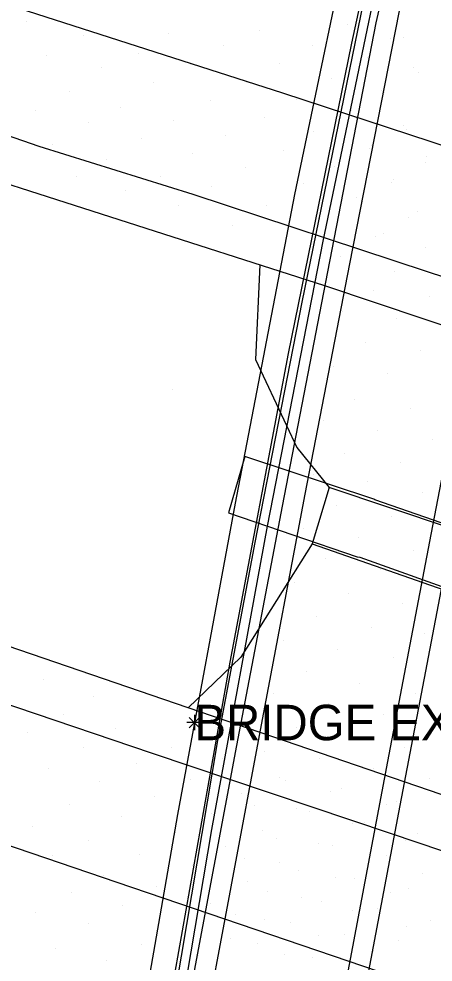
# Model space of a CAD drawing. Extents: x 1733582 to 1734070, y 467256 to 468256.
# Drawn here: x 1733820.12 to 1733841.15, y 467736.94 to 467784.83 of the extents above; entities that cross this region are included whole.
import ezdxf

# ---------------------------------------------------------------- set-up
doc = ezdxf.new("R2010")
doc.units = 0
for name, color, linetype in [('Default', 7, 'Continuous'), ('S_Bridge_Column_Square', 7, 'Continuous'), ('S_Bridge_Curb', 7, 'Continuous'), ('S_Bridge_Deck', 7, 'Continuous'), ('S_Bridge_Rail', 7, 'Continuous'), ('S_Ground_LevelString', 7, 'Continuous'), ('S_Ground_SpotElevation', 7, 'Continuous'), ('S_Guardrail_Beam', 7, 'Continuous'), ('S_Misc_MiscFeature', 7, 'Continuous'), ('S_Misc_MiscItems', 7, 'Continuous'), ('S_Roadway_Edge_Pavement', 7, 'Continuous'), ('S_Roadway_Painted_Lines', 7, 'Continuous'), ('S_Text', 7, 'Continuous')]:
    doc.layers.add(name, color=color, linetype=linetype)

# ---------------------------------------------------------------- blocks, each defined once
blk = doc.blocks.new('POINT_DISPLAY')
at = {"layer": 'Default'}
blk.add_line((0, 0), (0, 0), dxfattribs=at)

msp = doc.modelspace()

# ---------------------------------------------------------------- linework, layer by layer
at = {"layer": 'S_Bridge_Column_Square'}
msp.add_lwpolyline([(1733835.014, 467758.174), (1733846.976, 467754), (1733861.457, 467749.164), (1733862.347, 467752.05), (1733848.201, 467756.91), (1733835.866, 467761.044), (1733835.014, 467758.174)], dxfattribs=at)
at = {"layer": 'S_Bridge_Curb'}
msp.add_lwpolyline([(1733818.159, 467663.732), (1733819.385, 467674.582), (1733820.64, 467684.116), (1733822.243, 467697.564), (1733823.972, 467709.579), (1733825.87, 467722.342), (1733827.859, 467734.138), (1733830.216, 467748.192), (1733832.11, 467758.256), (1733834.51, 467770.45), (1733837.898, 467787.063), (1733840.865, 467800.549), (1733844.359, 467815.787), (1733847.831, 467829.289), (1733850.56, 467839.861), (1733853.05, 467849.061), (1733854.563, 467854.584)], dxfattribs=at)
at = {"layer": 'S_Bridge_Deck'}
msp.add_lwpolyline([(1733855.138, 467854.785), (1733853.086, 467847.693), (1733849.22, 467833.073), (1733845.482, 467818.291), (1733842.048, 467803.532), (1733838.704, 467788.663), (1733835.558, 467773.547), (1733832.728, 467759.072), (1733829.896, 467743.681), (1733827.379, 467728.743), (1733824.957, 467713.563), (1733822.869, 467698.529), (1733821.029, 467683.583), (1733819.201, 467668.729), (1733818.621, 467663.409)], dxfattribs=at)
at = {"layer": 'S_Bridge_Rail'}
msp.add_lwpolyline([(1733818.359, 467665.855), (1733819.171, 467673.048), (1733821.039, 467688.917), (1733823.113, 467704.785), (1733825.46, 467720.602), (1733828.058, 467736.434), (1733830.845, 467752.168), (1733833.805, 467767.85), (1733837.016, 467783.594), (1733840.405, 467799.172), (1733844.065, 467814.724), (1733847.908, 467830.326), (1733851.933, 467845.769), (1733853.853, 467852.641)], dxfattribs=at)
at = {"layer": 'S_Ground_LevelString'}
for points in [[(1733832.345, 467772.348), (1733832.13, 467767.533), (1733834.232, 467763.07), (1733835.866, 467761.044)], [(1733835.014, 467758.174), (1733831.391, 467752.425), (1733828.709, 467749.857)]]:
    msp.add_lwpolyline(points, dxfattribs=at)
at = {"layer": 'S_Guardrail_Beam'}
for points in [[(1733971.13, 467727.753), (1733959.189, 467731.849), (1733947.467, 467735.892), (1733935.587, 467740.11), (1733923.652, 467744.12), (1733911.999, 467748.09), (1733900.23, 467752.154), (1733888.348, 467756.158), (1733876.584, 467760.123), (1733864.636, 467764.075), (1733852.71, 467768.12), (1733840.864, 467771.985), (1733828.96, 467775.911), (1733821.157, 467778.362), (1733811.276, 467781.779), (1733806.138, 467783.487), (1733804.067, 467784.255), (1733803.797, 467784.235), (1733803.622, 467784.139), (1733803.485, 467783.985), (1733803.422, 467783.75), (1733803.437, 467783.569), (1733803.561, 467783.396)], [(1733779.584, 467763.162), (1733791.412, 467759.266), (1733803.188, 467755.466), (1733815.088, 467751.54), (1733826.834, 467747.566), (1733839.025, 467743.476), (1733850.692, 467739.538), (1733862.451, 467735.523), (1733874.35, 467731.517), (1733886.109, 467727.39), (1733889.984, 467726.018), (1733892.208, 467725.279), (1733893.28, 467725.008), (1733893.637, 467725.214), (1733893.817, 467725.531), (1733893.796, 467725.839), (1733893.658, 467726.063), (1733893.419, 467726.195)]]:
    msp.add_lwpolyline(points, dxfattribs=at)
at = {"layer": 'S_Misc_MiscFeature'}
for points in [[(1733819.146, 467662.128), (1733822.411, 467687.138), (1733825.625, 467712.064), (1733828.308, 467732.621), (1733831.184, 467747.947), (1733833.505, 467760.094), (1733835.806, 467771.99), (1733838.257, 467784.633), (1733839.477, 467789.916), (1733843.642, 467806.605), (1733849.69, 467830.62), (1733855.796, 467855.018)], [(1733820.122, 467661.91), (1733823.472, 467687.541), (1733826.672, 467712.367), (1733829.355, 467732.542), (1733832.44, 467748.988), (1733834.659, 467760.701), (1733836.916, 467772.404), (1733839.778, 467786.991), (1733844.946, 467807.685), (1733851.172, 467832.455), (1733856.733, 467854.727)], [(1733826.53, 467660.119), (1733830.278, 467688.775), (1733833.202, 467711.396), (1733835.635, 467730.109), (1733838.854, 467747.125), (1733841.053, 467758.65), (1733843.35, 467770.62), (1733845.821, 467783.336), (1733847.212, 467789.204), (1733851.47, 467806.186), (1733857.516, 467830.268), (1733863.15, 467852.64)], [(1733852.432, 467852.088), (1733847.956, 467835.582), (1733844.668, 467822.664), (1733840.962, 467807.205), (1733837.376, 467791.545), (1733834.11, 467775.918), (1733831.093, 467760.248), (1733828.17, 467744.438), (1733825.424, 467728.718), (1733822.802, 467711.353), (1733820.741, 467696.705), (1733817.897, 467673.275), (1733817.169, 467667.027)], [(1733864.079, 467852.275), (1733858.131, 467828.607), (1733852.049, 467804.339), (1733847.192, 467785.066), (1733844.207, 467769.696), (1733841.988, 467758.102), (1733839.394, 467744.549), (1733836.696, 467730.312), (1733833.835, 467708.583), (1733831.31, 467688.992), (1733827.509, 467659.844)], [(1733832.345, 467772.348), (1733832.13, 467767.533), (1733834.232, 467763.07), (1733835.866, 467761.044)], [(1733866.647, 467750.615), (1733860.076, 467752.833), (1733860.036, 467752.849), (1733852.751, 467755.357), (1733852.653, 467755.397), (1733845.408, 467757.906), (1733845.361, 467757.924), (1733838.187, 467760.422), (1733838.141, 467760.443), (1733831.583, 467762.612), (1733830.756, 467759.752), (1733837.3, 467757.526), (1733837.424, 467757.497), (1733844.577, 467754.95), (1733844.636, 467754.93), (1733851.762, 467752.482), (1733851.91, 467752.431), (1733859.188, 467749.921), (1733859.254, 467749.894), (1733865.861, 467747.686), (1733866.647, 467750.615)], [(1733835.014, 467758.174), (1733831.391, 467752.425), (1733828.709, 467749.857)]]:
    msp.add_lwpolyline(points, dxfattribs=at)
at = {"layer": 'S_Misc_MiscItems'}
for p, q in [((1733829.426, 467749.109), (1733828.64, 467749.109)), ((1733829.295, 467748.847), (1733828.771, 467749.371)), ((1733829.295, 467749.371), (1733828.771, 467748.847)), ((1733829.033, 467749.502), (1733829.033, 467748.716))]:
    msp.add_line(p, q, dxfattribs=at)
at = {"layer": 'S_Roadway_Edge_Pavement'}
for points in [[(1733611.876, 467844.635), (1733674.83, 467825.942), (1733744.192, 467804.366), (1733759.494, 467799.192), (1733788.268, 467787.576), (1733794.963, 467784.321), (1733814.735, 467777.995), (1733835.64, 467771.291), (1733878.809, 467756.802), (1733915.97, 467744.059), (1733950.334, 467732.351), (1733979.802, 467721.488), (1733993.679, 467716.295), (1734030.704, 467703.141), (1734054.753, 467695.101)], [(1734047.514, 467668.647), (1734012.708, 467681.197), (1733935.599, 467708.176), (1733908.807, 467722.422), (1733806.077, 467757.609), (1733715.329, 467786.896), (1733665.166, 467802.478), (1733604.388, 467822.173)]]:
    msp.add_lwpolyline(points, dxfattribs=at)
at = {"layer": 'S_Roadway_Painted_Lines'}
for points in [[(1733613.543, 467849.189), (1733648.882, 467838.819), (1733697.382, 467824.233), (1733741.485, 467810.479), (1733805.714, 467790.022), (1733833.501, 467781.081), (1733877.654, 467766.584), (1733913.643, 467754.586), (1734001.896, 467724.119), (1734057.373, 467704.28)], [(1733600.615, 467812.285), (1733624.074, 467805.253), (1733650.091, 467797.478), (1733690.162, 467785.254), (1733709.513, 467779.192), (1733740.833, 467769.059), (1733764.442, 467761.384), (1733801.856, 467748.917), (1733825.1, 467741.003), (1733865.745, 467727.157), (1733942.114, 467701.157), (1734018.088, 467674.904), (1734046.328, 467664.849)]]:
    msp.add_lwpolyline(points, dxfattribs=at)

# ---------------------------------------------------------------- block references
at = {"layer": 'S_Ground_SpotElevation'}
for p in [(1733820.496, 467784.719), (1733836.799, 467784.544), (1733827.736, 467784.083), (1733832.351, 467784.227), (1733823.376, 467784.01), (1733839, 467783.835), (1733839.666, 467783.877), (1733826.205, 467783.075), (1733830.526, 467783.464), (1733835.02, 467783.497), (1733821.502, 467782.966), (1733837.825, 467782.891), (1733824.334, 467782.353), (1733828.838, 467782.506), (1733833.355, 467782.558), (1733840.172, 467782.387), (1733835.995, 467781.799), (1733840.407, 467782.096), (1733822.669, 467781.165), (1733826.966, 467781.579), (1733831.671, 467781.607), (1733838.541, 467781.198), (1733829.852, 467780.696), (1733834.219, 467780.756), (1733838.67, 467781.093), (1733825.27, 467780.35), (1733820.949, 467780.18), (1733832.569, 467779.826), (1733837.015, 467780.162), (1733823.677, 467779.563), (1733827.992, 467779.699), (1733839.654, 467779.439), (1733826.335, 467778.769), (1733830.633, 467778.891), (1733835.09, 467779.129), (1733839.791, 467779.225), (1733821.805, 467778.452), (1733838.047, 467778.429), (1733828.939, 467777.983), (1733833.533, 467778.129), (1733837.925, 467778.26), (1733840.836, 467777.846), (1733824.558, 467777.673), (1733836.123, 467777.337), (1733840.765, 467777.535), (1733823.044, 467776.842), (1733831.61, 467777.265), (1733827.324, 467776.821), (1733834.56, 467776.492), (1733839.032, 467776.53), (1733839.159, 467776.678), (1733825.541, 467776.14), (1733829.888, 467776.314), (1733837.283, 467775.741), (1733837.495, 467775.539), (1733828.203, 467775.355), (1733832.693, 467775.335), (1733840.338, 467775.07), (1733835.401, 467774.68), (1733839.896, 467774.748), (1733830.96, 467774.352), (1733833.675, 467773.579), (1733838.242, 467773.787), (1733838.648, 467773.956), (1733840.75, 467773.218), (1733836.472, 467772.781), (1733837.035, 467772.942), (1733839.847, 467772.319), (1733839.198, 467772.019), (1733838.149, 467771.036), (1733840.979, 467770.749), (1733836.568, 467769.98), (1733839.291, 467769.633), (1733837.72, 467768.395), (1733840.513, 467767.982), (1733836.075, 467767.196), (1733838.838, 467766.843), (1733827.909, 467766), (1733837.157, 467765.509), (1733839.996, 467765.067), (1733835.589, 467764.435), (1733838.322, 467763.932), (1733841.141, 467763.489), (1733836.671, 467762.744), (1733839.513, 467762.318), (1733835.089, 467761.695), (1733837.833, 467761.35), (1733840.632, 467760.772), (1733836.228, 467760.134), (1733839.013, 467759.576), (1733834.555, 467758.96), (1733837.374, 467758.502), (1733840.154, 467757.845), (1733835.688, 467757.417), (1733838.498, 467756.853), (1733834.093, 467756.195), (1733836.857, 467755.675), (1733839.614, 467755.143), (1733835.235, 467754.467), (1733838.005, 467753.953), (1733840.715, 467753.635), (1733833.562, 467753.278), (1733836.296, 467752.815), (1733839.155, 467752.403), (1733834.738, 467751.712), (1733821.367, 467751.275), (1733837.437, 467751.093), (1733833.054, 467750.561), (1733840.254, 467750.56), (1733823.895, 467750.442), (1733835.819, 467750.061), (1733822.361, 467749.519), (1733838.638, 467749.506), (1733820.554, 467748.598), (1733825.043, 467748.823), (1733834.221, 467748.839), (1733836.931, 467748.377), (1733823.377, 467747.859), (1733827.848, 467747.837), (1733832.569, 467747.638), (1733839.703, 467747.86), (1733830.453, 467747.262), (1733835.386, 467747.297), (1733821.623, 467746.765), (1733826.093, 467747.025), (1733838.143, 467746.782), (1733828.84, 467746.199), (1733833.362, 467746.314), (1733840.959, 467746.247), (1733824.205, 467746.113), (1733833.661, 467746.158), (1733836.508, 467745.778), (1733826.998, 467745.328), (1733831.397, 467745.498), (1733835.953, 467745.627), (1733822.684, 467744.967), (1733832.089, 467744.907), (1733834.235, 467744.757), (1733838.78, 467744.953), (1733839.287, 467745.087), (1733825.313, 467744.339), (1733829.911, 467744.48), (1733834.851, 467744.593), (1733820.798, 467743.806), (1733837.057, 467744), (1733837.678, 467744.043), (1733828.064, 467743.515), (1733832.478, 467743.646), (1733840.374, 467743.453), (1733823.678, 467743.105), (1733833.205, 467743.233), (1733835.344, 467742.955), (1733836.034, 467742.865), (1733839.767, 467743.143), (1733826.221, 467742.385), (1733830.627, 467742.831), (1733838.809, 467742.362), (1733821.841, 467742.341), (1733831.594, 467742.218), (1733833.362, 467741.995), (1733837.917, 467742.282), (1733828.954, 467741.857), (1733834.319, 467741.575), (1733840.612, 467741.421), (1733824.403, 467741.344), (1733831.722, 467741.055), (1733836.208, 467741.264), (1733837.178, 467741.174), (1733822.779, 467740.497), (1733827.11, 467740.774), (1733832.749, 467740.527), (1733838.97, 467740.463), (1733839.923, 467740.703), (1733834.485, 467740.239), (1733835.481, 467740.038), (1733825.357, 467739.805), (1733829.834, 467739.932), (1733837.056, 467739.57), (1733838.337, 467739.647), (1733820.958, 467739.455), (1733831.115, 467739.365), (1733832.575, 467739.092), (1733841.041, 467739.055), (1733823.673, 467738.894), (1733828.332, 467738.891), (1733833.909, 467738.963), (1733839.792, 467738.745), (1733830.839, 467738.131), (1733835.321, 467738.271), (1733836.665, 467738.354), (1733821.973, 467737.658), (1733826.322, 467737.849), (1733832.238, 467737.874), (1733839.404, 467738.027), (1733829.227, 467737.297), (1733833.59, 467737.32), (1733835.01, 467737.197), (1733838.116, 467737.492), (1733824.563, 467737.003)]:
    msp.add_blockref('POINT_DISPLAY', p, dxfattribs=at)

# ---------------------------------------------------------------- texts
at = {"layer": 'S_Text'}
msp.add_text('BRIDGE EXTENTS', height=1.8, dxfattribs=at).set_placement((1733829.033, 467748.209))

doc.saveas('drawing.dxf')
